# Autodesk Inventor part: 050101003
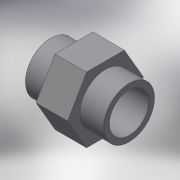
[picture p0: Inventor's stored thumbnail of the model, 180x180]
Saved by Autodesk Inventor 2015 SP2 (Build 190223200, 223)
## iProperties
Created: 2017-10
Part Number: 050101003
Material: Generic
Description: PLASSON THREADED SOCKET PVC 3/8"
Document SubType Name: Modeling
Designer: KIM
Density: 1 g/cm^3
Appearance: Default
Author: KIM
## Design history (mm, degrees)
derived "050101.ipt"
feature "Solid1::050101.ipt"
tag "TaggingFeature1"
body "Solid1"
other parameters: "d1" = 14.95, "d2" = 25, "d3" = 14.95, "d4" = 13.455, "d5" = 13, "d6" = 13, "d7" = 19.435, "d8" = 19.435, "d10" = 9.1, "d13" = 0, "d14" = 0.1495, "d15" = 12, "G_" = 14.95, "C_" = 25, "B_" = 12, "lt_" = 13
